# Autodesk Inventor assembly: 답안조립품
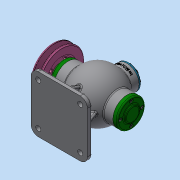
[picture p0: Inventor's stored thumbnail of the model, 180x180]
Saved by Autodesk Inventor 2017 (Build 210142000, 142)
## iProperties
Part Number: 답안조립품
Material: 일반
Document SubType Name: Assembly
Designer: MRC
Author: MRC
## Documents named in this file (16)
- C:\Users\MRC\Desktop\720811V1006\답안조립품.iam
- C:\Users\MRC\Desktop\720811V1006\본체.ipt
- C:\Users\MRC\Desktop\720811V1006\V-벨트풀리.ipt
- C:\Users\MRC\Desktop\720811V1006\너트 M8.ipt
- C:\Users\MRC\Desktop\720811V1006\뒤커버.ipt
- C:\Users\MRC\Desktop\720811V1006\베어링- 6202.ipt
- KS B 2023 - 6202 - 15 x 35 x 11 - 7.8.ipt
- C:\Users\MRC\Desktop\720811V1006\볼트 M4 x 12.ipt
- C:\Users\MRC\Desktop\720811V1006\볼트 M4 x 16.ipt
- C:\Users\MRC\Desktop\720811V1006\상부커버.ipt
- C:\Users\MRC\Desktop\720811V1006\슬라이드.ipt
- C:\Users\MRC\Desktop\720811V1006\앞커버.ipt
- C:\Users\MRC\Desktop\720811V1006\오일실 15 30 7.ipt
- C:\Users\MRC\Desktop\720811V1006\칼라.ipt
- C:\Users\MRC\Desktop\720811V1006\키 4 x 4 x 12.ipt
- C:\Users\MRC\Desktop\720811V1006\편심축.ipt
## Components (15 placed, 4 different names)
1. V-벨트풀리:1
2. KS B 2023 - 6202 - 15 x 35 x 11 - 7.8:1
3. KS B 2023 - 6202 - 15 x 35 x 11 - 7.8:2
4. ISO 4762 M4 x 16:1
5. ISO 4762 M4 x 16:2
6. ISO 4762 M4 x 16:3
7. ISO 4762 M4 x 16:4
8. ISO 4762 M4 x 16:5
9. ISO 4762 M4 x 16:6
10. ISO 4762 M4 x 16:7
11. ISO 4762 M4 x 16:8
12. KS B 1021 - 에 따름 ISO 1207 - 미터 A  M 4 x 12:1
13. KS B 1021 - 에 따름 ISO 1207 - 미터 A  M 4 x 12:2
14. KS B 1021 - 에 따름 ISO 1207 - 미터 A  M 4 x 12:3
15. KS B 1021 - 에 따름 ISO 1207 - 미터 A  M 4 x 12:4
